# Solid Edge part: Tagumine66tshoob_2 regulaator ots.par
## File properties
Author: KULL
Template: Iso Metric Part.par
Last saved by: KULL
Revision: 10
Application: Solid Edge
Accuracy: 0,990
Face Style: Model Default
Fill Style: Normal
Coef. of Thermal Exp: 0.0
Thermal Conductivity: 0.0
Specific Heat: 0.0
Modulus of Elasticity: 0.0
Poisson's Ratio: 0.0
Yield Stress: 0.0
Ultimate Stress: 0.0
Elongation: 0.0
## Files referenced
..\..\Rover_ASM.asm
D:\Solid edge leong\Solid edge Sync practice\ROVER_Heiko_Kull_EKSAM\Raam\Chassy_1.par
D:\Solid edge leong\Solid edge Sync practice\ROVER_Heiko_Kull_EKSAM\Roolimise_jupid\frontsteering_1.par
QD:\Solid edge leong\Solid edge Sync practice\ROVER_Heiko_Kull_EKSAM\Rover_ASM.asm
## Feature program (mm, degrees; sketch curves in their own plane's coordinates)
helix cutout "HelixCutout_1"  NumberOfTurns = 20
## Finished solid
Body 1: sheet body, 1 face, 170 edges, 170 vertices.
  Faces by surface: plane 1
  Edges by curve: line 83, intersection 78, circle 9
Body 2: solid body, 13 faces, 19 edges, 8 vertices.
  Faces by surface: plane 3, torus 3, cylinder 2, sphere 2, spline 2, cone 1
  Edges by curve: line 8, circle 7, spline 4
Body 3: sheet body, 1 face, 1 edge, 0 vertices.
  Faces by surface: sphere 1
  Edges by curve: circle 1
Bounding box of the edges (mm; curved faces can reach further): 349.394 x 56.210 x 10.181, from (-347.2122, 59.4596, 47.368) to (2.1818, 115.6693, 57.5489).
Cylindrical faces by radius (mm): R1.2428 x1, R2 x1
Conical faces (half-angle, radius in mm at the cone's reference point): 45.9967 deg R2.8772 x1
Toroidal faces (ring radius, tube radius in mm): R3.1566 r0.2 x1, R4 r2 x1, R4.277 r0.6 x1
Spherical faces by radius (mm): R4 x2, R6 x1
Planar faces by outward normal: +x 1, -x 1, oblique 1
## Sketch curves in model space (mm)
line (-342.46, 45, 56.811) -> (-342.46, 109.6693, 51.2645)
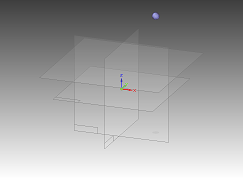
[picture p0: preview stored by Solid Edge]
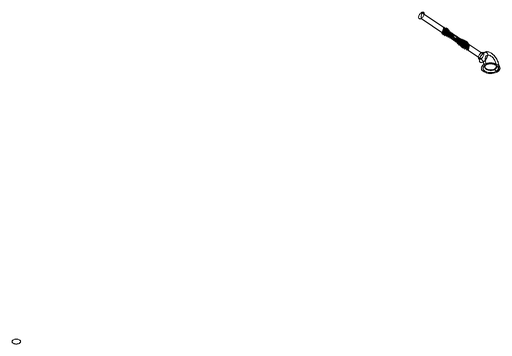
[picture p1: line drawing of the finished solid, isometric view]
